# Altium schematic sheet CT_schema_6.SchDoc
size 278 x 170 mm
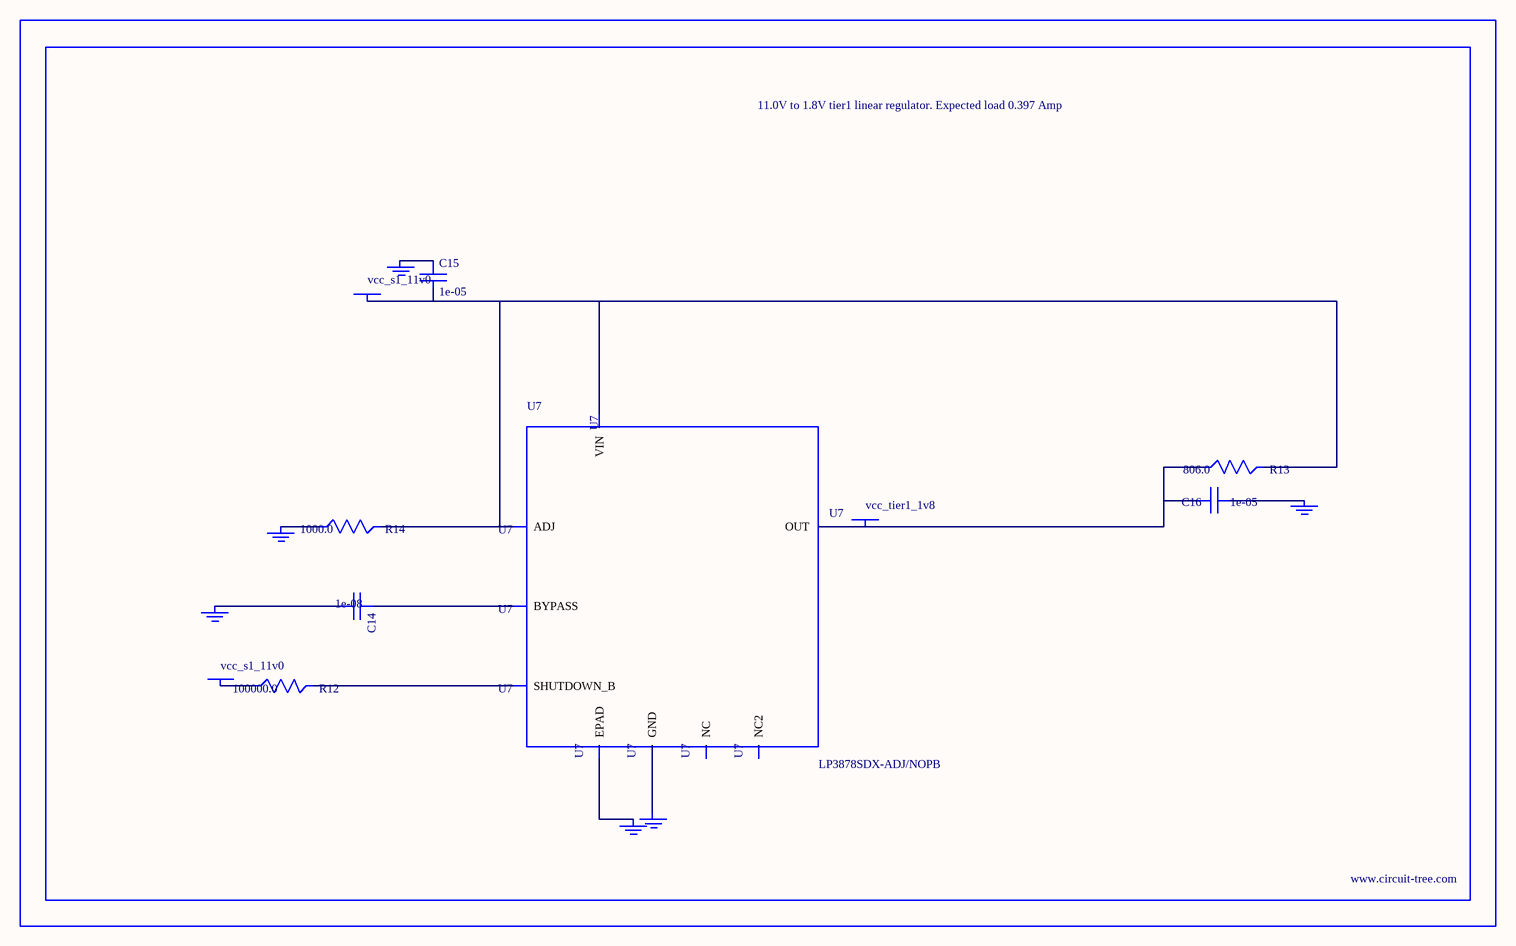
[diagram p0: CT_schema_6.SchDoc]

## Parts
BORDER5  (no value)
C14  1e-08  [C0402]
C15  1e-05  [C1206]
C16  1e-05  [C0805]
GND_INSTANCE_5_0  (no value)
GND_INSTANCE_5_1  (no value)
GND_INSTANCE_5_2  (no value)
GND_INSTANCE_5_3  (no value)
GND_INSTANCE_5_4  (no value)
GND_INSTANCE_5_5  (no value)
POWER_INSTANCE_5_0  vcc_s1_11v0
POWER_INSTANCE_5_1  vcc_s1_11v0
POWER_INSTANCE_5_2  vcc_tier1_1v8
R12  100000.0  [R0603]
R13  806.0  [R0603]
R14  1000.0  [R0603]
U7  LP3878SDX-ADJ/NOPB  [WSON-8]

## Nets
NetC14_1: C14.1 U7.1(BYPASS)
NetC14_2: C14.2 GND_INSTANCE_5_0.0(GND)
NetC15_1: C15.1 GND_INSTANCE_5_1.0(GND)
NetC15_2: C15.2 POWER_INSTANCE_5_0.0(PWR) R13.2 R14.2 U7.4(VIN) U7.6(ADJ)
NetC16_1: C16.1 GND_INSTANCE_5_2.0(GND)
NetC16_2: C16.2 POWER_INSTANCE_5_2.0(PWR) R13.1 U7.5(OUT)
NetGND_INSTANCE_5_3_0: GND_INSTANCE_5_3.0(GND) R14.1
NetGND_INSTANCE_5_4_0: GND_INSTANCE_5_4.0(GND) U7.PAD(EPAD)
NetGND_INSTANCE_5_5_0: GND_INSTANCE_5_5.0(GND) U7.3(GND)
NetPOWER_INSTANCE_5_1_0: POWER_INSTANCE_5_1.0(PWR) R12.1
NetR12_2: R12.2 U7.8(SHUTDOWN_B)

Not connected (* = marked no-connect by the designer): U7 2(NC) 7(NC2)

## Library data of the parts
BORDER5 = BORDER_PAGE5
C14 = C0402C103K3RAC
C15 = C1206C106K3RACTU
C16 = GRM219R60J106ME19D
GND_INSTANCE_5_0-GND_INSTANCE_5_5 = GND
POWER_INSTANCE_5_0-POWER_INSTANCE_5_2 = PWR
R12 = RC0603JR-07100KL
R13 = ERJ-3EKF8060V
R14 = RC0603JR-071KL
